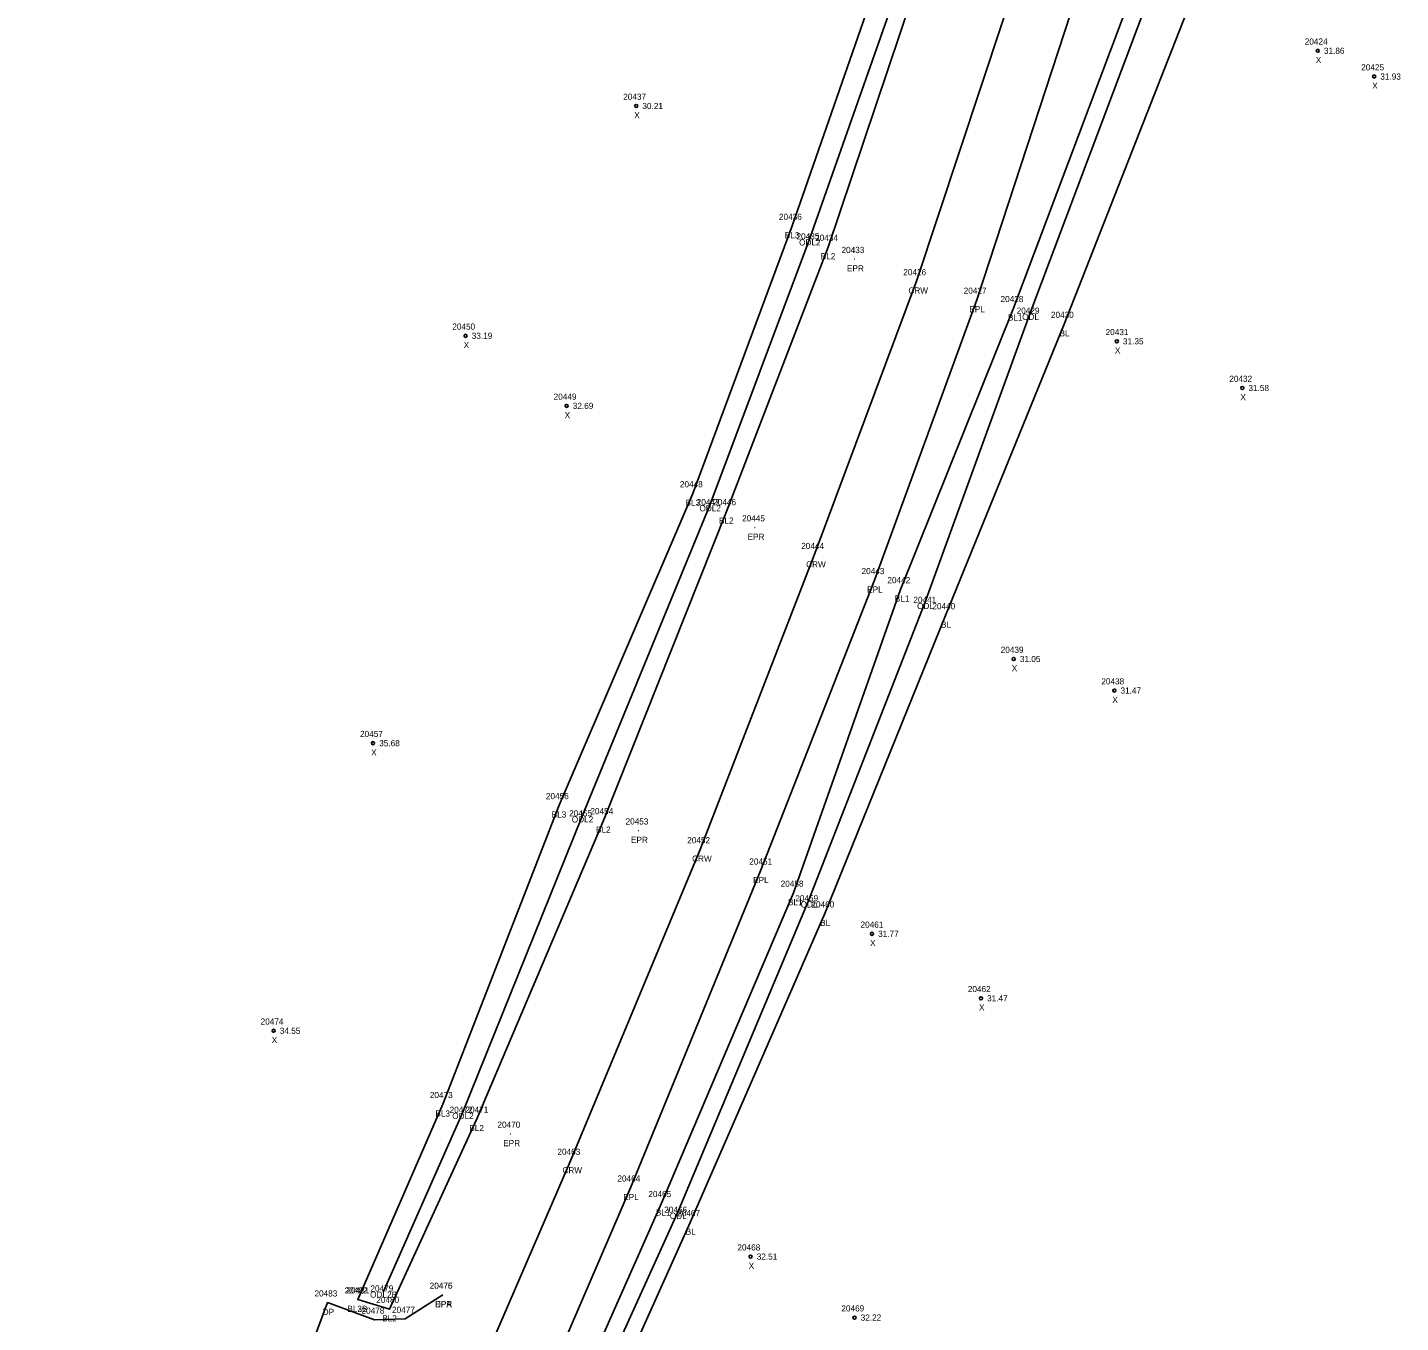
# Model space of a CAD drawing. Extents: x 2432729 to 2433340, y 684958 to 688103.
# Drawn here: x 2432890.4 to 2433113.8, y 685416.3 to 685627 of the extents above; entities that cross this region are included whole.
import ezdxf

# ---------------------------------------------------------------- set-up
doc = ezdxf.new("R2010")
doc.units = 0
for name, color, linetype in [('RD_DTM_BkLn1', 7, 'Continuous'), ('RD_EX_Driveway', 7, 'Continuous'), ('RD_EX_Driveway_txCode', 7, 'Continuous'), ('RD_EX_H2O', 7, 'Continuous'), ('RD_EX_H2O_txCode', 7, 'Continuous'), ('RD_EX_Road', 7, 'Continuous'), ('RD_EX_Road_txCode', 7, 'Continuous'), ('RD_Sketch8', 7, 'Continuous'), ('RD_SMD_Locator', 7, 'Continuous'), ('RD_SMD_Misc', 7, 'Continuous')]:
    doc.layers.add(name, color=color, linetype=linetype)

msp = doc.modelspace()

# ---------------------------------------------------------------- linework, layer by layer
at = {"layer": 'RD_DTM_BkLn1'}
for points in [[(2433044.85, 685699.14), (2433032.33, 685645.11), (2433014.81, 685594.7), (2432998.67, 685551.2), (2432976.89, 685500.47), (2432957.99, 685451.85), (2432944.14, 685420.07)], [(2433052.78, 685695.75), (2433038.11, 685643.19), (2433020.67, 685591.28), (2433004.11, 685548.28), (2432984.11, 685498.02), (2432963.5, 685449.48), (2432949.33, 685418.54), (2432944.14, 685420.07)], [(2433067.41, 685690.62), (2433052.49, 685638.4), (2433035.04, 685585.7), (2433018.41, 685541.16), (2432999.85, 685493.3), (2432978.77, 685442.62), (2432938.71, 685349.86), (2432898.27, 685257.39), (2432861.69, 685174.74), (2432859.51, 685169.85), (2432818.13, 685076.09), (2432777.09, 684983.43)], [(2433087.86, 685684.95), (2433070.24, 685632.97), (2433050.83, 685581.32), (2433032.43, 685535.6), (2433015.06, 685486.22), (2432993.56, 685435.75), (2432952.83, 685343.93), (2432911.02, 685251.28), (2432891.52, 685205.36), (2432897.43, 685203.55)], [(2433102.05, 685679.62), (2433079.53, 685630.77), (2433059.07, 685578.75), (2433039.78, 685531.36), (2433020.13, 685482.85), (2432998.25, 685432.63), (2432957.4, 685341.66), (2432916.69, 685248.39), (2432897.43, 685203.55)]]:
    msp.add_lwpolyline(points, dxfattribs=at)
at = {"layer": 'RD_EX_Driveway'}
msp.add_lwpolyline([(2432957.98, 685420.84), (2432951.85, 685416.92), (2432946.88, 685416.78), (2432939.23, 685419.58), (2432935.03, 685408.39), (2432941.96, 685403.86), (2432946.89, 685398.08), (2432946.33, 685394.97)], dxfattribs=at)
at = {"layer": 'RD_EX_H2O'}
for points in [[(2433050.34, 685696.78), (2433035.7, 685643.89), (2433017.64, 685592.53), (2433001.42, 685549.29), (2432980.66, 685498.68), (2432961.21, 685450.45), (2432948.33, 685421.39)], [(2433091.72, 685683.25), (2433072.97, 685632.18), (2433053.46, 685580.43), (2433036.38, 685533.4), (2433017.44, 685484.85), (2432996.16, 685434.2), (2432954.84, 685343.07), (2432912.85, 685250.04), (2432894.77, 685206.8)]]:
    msp.add_lwpolyline(points, dxfattribs=at)
at = {"layer": 'RD_EX_Road'}
msp.add_lwpolyline([(2433077.66, 685687.92), (2433062.23, 685635.7), (2433044.84, 685582.68), (2433028.22, 685537.07), (2433009.68, 685489.83), (2432988.53, 685438.27), (2432948.62, 685345.62), (2432907.86, 685252.74), (2432887.37, 685205.96), (2432872.08, 685170.45), (2432827.85, 685071.69), (2432787.31, 684979.59)], dxfattribs=at)
at = {"layer": 'RD_SMD_Locator'}
for centre, radius in [((2433100.32, 685623.2), 0.25), ((2433109.49, 685619.01), 0.25), ((2432989.45, 685614.22), 0.25), ((2433014.81, 685594.7), 0.001), ((2433017.64, 685592.53), 0.001), ((2433020.67, 685591.28), 0.001), ((2433024.96, 685589.31), 0.001), ((2433035.04, 685585.7), 0.001), ((2433044.84, 685582.68), 0.001), ((2433050.83, 685581.32), 0.001), ((2433053.46, 685580.43), 0.001), ((2432961.69, 685576.84), 0.25), ((2433059.07, 685578.75), 0.001), ((2433067.63, 685575.95), 0.25), ((2433088.04, 685568.35), 0.25), ((2432978.13, 685565.44), 0.25), ((2432998.67, 685551.2), 0.001), ((2433001.42, 685549.29), 0.001), ((2433004.11, 685548.28), 0.001), ((2433008.78, 685545.65), 0.001), ((2433018.41, 685541.16), 0.001), ((2433028.22, 685537.07), 0.001), ((2433032.43, 685535.6), 0.001), ((2433036.38, 685533.4), 0.001), ((2433039.78, 685531.36), 0.001), ((2433050.86, 685524.27), 0.25), ((2433067.23, 685519.14), 0.25), ((2432946.64, 685510.58), 0.25), ((2432976.89, 685500.47), 0.001), ((2432980.66, 685498.68), 0.001), ((2432984.11, 685498.02), 0.001), ((2432989.83, 685496.35), 0.001), ((2432999.85, 685493.3), 0.001), ((2433009.68, 685489.83), 0.001), ((2433015.06, 685486.22), 0.001), ((2433017.44, 685484.85), 0.001), ((2433020.13, 685482.85), 0.001), ((2433027.8, 685479.57), 0.25), ((2433045.53, 685469.09), 0.25), ((2432930.47, 685463.8), 0.25), ((2432957.99, 685451.85), 0.001), ((2432961.21, 685450.45), 0.001), ((2432963.5, 685449.48), 0.001), ((2432969.04, 685447.03), 0.001), ((2432978.77, 685442.62), 0.001), ((2432988.53, 685438.27), 0.001), ((2432993.56, 685435.75), 0.001), ((2432996.16, 685434.2), 0.001), ((2432998.25, 685432.63), 0.001), ((2433008.05, 685427.07), 0.25), ((2432948.33, 685421.39), 0.001), ((2432957.98, 685420.84), 0.001), ((2432957.98, 685420.84), 0.001), ((2432939.23, 685419.58), 0.001), ((2432944.14, 685420.07), 0.001), ((2432944.14, 685420.07), 0.001), ((2432949.33, 685418.54), 0.001), ((2432946.88, 685416.78), 0.001), ((2432951.85, 685416.92), 0.001), ((2433024.96, 685417.15), 0.25)]:
    msp.add_circle(centre, radius, dxfattribs=at)

# ---------------------------------------------------------------- texts
at = {"layer": 'RD_EX_Driveway_txCode'}
for s, p in [('20476', (2432955.84, 685421.84)), ('20483', (2432937.11, 685420.58)), ('DP', (2432938.45, 685417.58)), ('20478', (2432944.76, 685417.78)), ('20477', (2432949.73, 685417.92)), ('DPA', (2432956.71, 685418.84))]:
    msp.add_text(s, height=1, dxfattribs=at).set_placement(p)
at = {"layer": 'RD_EX_H2O_txCode'}
for s, p in [('20435', (2433015.52, 685592.53)), ('ODL2', (2433015.94, 685591.53)), ('20429', (2433051.34, 685580.43)), ('ODL', (2433052.22, 685579.43)), ('20447', (2432999.3, 685549.29)), ('ODL2', (2432999.73, 685548.29)), ('20441', (2433034.54, 685533.4)), ('ODL', (2433035.13, 685532.4)), ('20455', (2432978.54, 685498.68)), ('ODL2', (2432978.97, 685497.68)), ('20459', (2433015.32, 685484.85)), ('ODL', (2433016.19, 685483.85)), ('20472', (2432959.09, 685450.45)), ('ODL2', (2432959.51, 685449.45)), ('20466', (2432994, 685434.2)), ('ODL', (2432994.92, 685433.2)), ('ODL2B', (2432946.16, 685420.39)), ('20479', (2432946.21, 685421.39))]:
    msp.add_text(s, height=1, dxfattribs=at).set_placement(p)
at = {"layer": 'RD_EX_Road_txCode'}
for s, p in [('20433', (2433022.84, 685590.31)), ('EPR', (2433023.73, 685587.31)), ('20427', (2433042.72, 685583.68)), ('EPL', (2433043.63, 685580.68)), ('20445', (2433006.67, 685546.65)), ('EPR', (2433007.56, 685543.65)), ('20443', (2433026.1, 685538.07)), ('EPL', (2433027.01, 685535.07)), ('20453', (2432987.71, 685497.35)), ('EPR', (2432988.6, 685494.35)), ('20451', (2433007.84, 685490.83)), ('EPL', (2433008.47, 685487.83)), ('20470', (2432966.88, 685448.03)), ('EPR', (2432967.81, 685445.03)), ('20464', (2432986.39, 685439.27)), ('EPL', (2432987.33, 685436.27)), ('20475', (2432955.86, 685421.84)), ('EPR', (2432956.75, 685418.84))]:
    msp.add_text(s, height=1, dxfattribs=at).set_placement(p)
at = {"layer": 'RD_Sketch8'}
for s, p in [('20424', (2433098.2, 685624.2)), ('X', (2433100, 685621.2)), ('31.86', (2433101.32, 685622.7)), ('20425', (2433107.38, 685620.01)), ('31.93', (2433110.49, 685618.51)), ('X', (2433109.18, 685617.01)), ('20437', (2432987.33, 685615.22)), ('X', (2432989.14, 685612.22)), ('30.21', (2432990.45, 685613.72)), ('20450', (2432959.53, 685577.84)), ('33.19', (2432962.69, 685576.34)), ('20431', (2433065.8, 685576.95)), ('X', (2432961.38, 685574.84)), ('X', (2433067.32, 685573.95)), ('31.35', (2433068.63, 685575.45)), ('20432', (2433085.92, 685569.35)), ('31.58', (2433089.04, 685567.85)), ('20449', (2432976.01, 685566.44)), ('32.69', (2432979.13, 685564.94)), ('X', (2433087.73, 685566.35)), ('X', (2432977.81, 685563.44)), ('20439', (2433048.74, 685525.27)), ('31.05', (2433051.86, 685523.77)), ('X', (2433050.54, 685522.27)), ('20438', (2433065.11, 685520.14)), ('31.47', (2433068.23, 685518.64)), ('X', (2433066.91, 685517.14)), ('20457', (2432944.52, 685511.58)), ('35.68', (2432947.64, 685510.08)), ('X', (2432946.33, 685508.58)), ('20461', (2433025.94, 685480.57)), ('31.77', (2433028.8, 685479.07)), ('X', (2433027.49, 685477.57)), ('20462', (2433043.39, 685470.09)), ('X', (2433045.22, 685467.09)), ('31.47', (2433046.53, 685468.59)), ('20474', (2432928.35, 685464.8)), ('34.55', (2432931.47, 685463.3)), ('X', (2432930.15, 685461.8)), ('20468', (2433005.91, 685428.07)), ('32.51', (2433009.05, 685426.57)), ('X', (2433007.74, 685425.07)), ('20469', (2433022.82, 685418.15)), ('32.22', (2433025.96, 685416.65))]:
    msp.add_text(s, height=1, dxfattribs=at).set_placement(p)
at = {"layer": 'RD_SMD_Misc'}
for s, p in [('20436', (2433012.67, 685595.7)), ('BL3', (2433013.61, 685592.7)), ('20434', (2433018.55, 685592.28)), ('BL2', (2433019.46, 685589.28)), ('20426', (2433032.9, 685586.7)), ('CRW', (2433033.72, 685583.7)), ('20428', (2433048.71, 685582.32)), ('BL1', (2433049.91, 685579.32)), ('20430', (2433056.91, 685579.75)), ('BL', (2433058.31, 685576.75)), ('20448', (2432996.55, 685552.2)), ('BL3', (2432997.47, 685549.2)), ('20446', (2433001.97, 685549.28)), ('BL2', (2433002.91, 685546.28)), ('20444', (2433016.29, 685542.16)), ('CRW', (2433017.09, 685539.16)), ('20442', (2433030.31, 685536.6)), ('BL1', (2433031.51, 685533.6)), ('20440', (2433037.62, 685532.36)), ('BL', (2433039.03, 685529.36)), ('20456', (2432974.75, 685501.47)), ('BL3', (2432975.69, 685498.47)), ('20454', (2432981.99, 685499.02)), ('BL2', (2432982.91, 685496.02)), ('20452', (2432997.74, 685494.3)), ('CRW', (2432998.54, 685491.3)), ('20458', (2433012.94, 685487.22)), ('BL1', (2433014.14, 685484.22)), ('20460', (2433017.95, 685483.85)), ('BL', (2433019.37, 685480.85)), ('20473', (2432955.87, 685452.85)), ('BL3', (2432956.78, 685449.85)), ('20471', (2432961.67, 685450.48)), ('BL2', (2432962.3, 685447.48)), ('20463', (2432976.63, 685443.62)), ('CRW', (2432977.45, 685440.62)), ('20465', (2432991.42, 685436.75)), ('BL1', (2432992.64, 685433.75)), ('20467', (2432996.11, 685433.63)), ('BL', (2432997.5, 685430.63)), ('20482', (2432942.02, 685421.07)), ('20481', (2432942.3, 685421.07)), ('20480', (2432947.17, 685419.54)), ('BL2B', (2432942.46, 685418.07)), ('BL3B', (2432942.46, 685418.07)), ('BL2', (2432948.13, 685416.54))]:
    msp.add_text(s, height=1, dxfattribs=at).set_placement(p)

doc.saveas('drawing.dxf')
